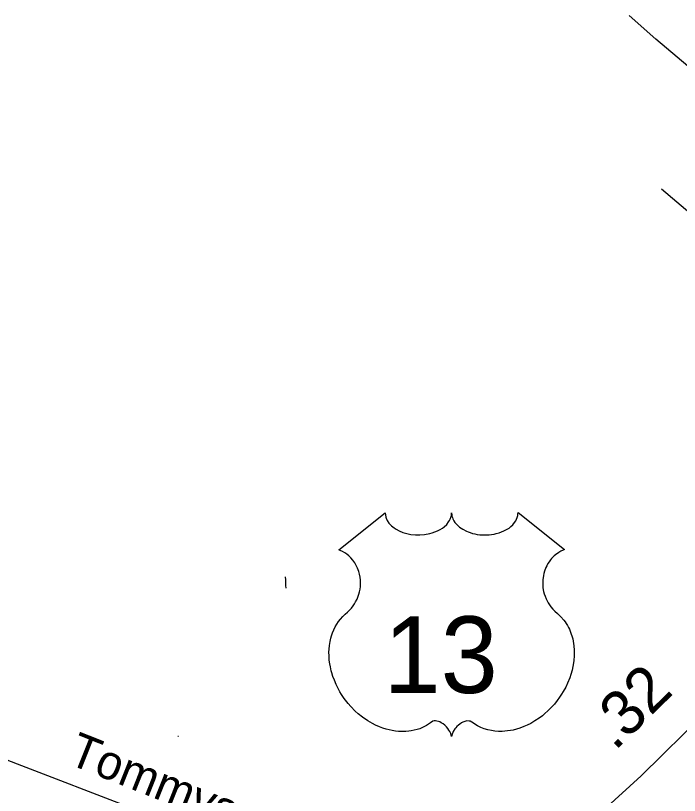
# Model space of a CAD drawing. Extents: x 2315291 to 2336543, y 597177 to 615230.
# Drawn here: x 2325292 to 2327131, y 602347 to 604507 of the extents above; entities that cross this region are included whole.
import ezdxf

# ---------------------------------------------------------------- set-up
doc = ezdxf.new("R2010")
doc.units = 0
for name, color, linetype in [('Exist Hydrographic Creek Single Shore', 7, 'Continuous'), ('Exist Road Non-System Type 51', 7, 'Continuous'), ('Exist Road Primary US Attributed', 7, 'Continuous'), ('Exist Road Primary US Mileage Tenths English Label', 7, 'Continuous'), ('Exist Road Primary US Shield CELL', 7, 'Continuous'), ('Exist Road Primary US Shield Number Label', 7, 'Continuous'), ('Exist Road Secondary Type 51 Attributed', 7, 'Continuous'), ('Exist Road Secondary Type 51 Label', 7, 'Continuous')]:
    doc.layers.add(name, color=color, linetype=linetype)

msp = doc.modelspace()

# ---------------------------------------------------------------- linework, layer by layer
at = {"layer": 'Exist Hydrographic Creek Single Shore'}
msp.add_lwpolyline([(2330983.5, 600534.7), (2330925.5, 600542.2), (2330547.5, 600822.3), (2330210.4, 601169.6), (2329763.4, 601712.7), (2329619.5, 601920.2), (2329459.3, 602110.6), (2329232.3, 602275.3), (2328880.5, 602461.4), (2328496.4, 602590.1), (2328144.3, 602763), (2328109.5, 602896.1), (2328072.4, 603219.6), (2327695.5, 603483.2), (2327485.3, 603638.8), (2327451.5, 603712.9), (2327081.3, 604026.1)], dxfattribs=at)
at = {"layer": 'Exist Road Non-System Type 51'}
msp.add_lwpolyline([(2327487.4, 604340.7), (2327469.1, 604290.7), (2327460.7, 604265.6), (2327450.7, 604250.6), (2327439.1, 604237.3), (2327420.7, 604228.9), (2327390.7, 604225.6), (2327355.7, 604227.3), (2327322.4, 604235.6), (2327285.7, 604250.6), (2327249, 604280.7), (2327184, 604341.5), (2327065.6, 604441.6), (2326992.3, 604506.7)], dxfattribs=at)
at = {"layer": 'Exist Road Primary US Attributed'}
msp.add_lwpolyline([(2326507.1, 601954.4), (2326687.2, 602106.2), (2326920.6, 602305.6), (2327025.6, 602400.6), (2327204, 602575.8), (2327489.1, 602864.4), (2327740.8, 603109.6)], dxfattribs=at)
at = {"layer": 'Exist Road Primary US Shield CELL'}
for p, q in [((2326187.4, 603026.9), (2326316, 603129.4)), ((2326316, 603129.4), (2326316.4, 603124)), ((2326499.5, 603122.5), (2326500, 603129.6)), ((2326500, 603129.6), (2326500.5, 603123.7)), ((2326683.3, 603121.5), (2326684, 603125.9)), ((2326684, 603125.9), (2326684.1, 603129.8)), ((2326684.1, 603129.8), (2326812.7, 603027.3)), ((2326316.4, 603124), (2326317.6, 603117.7)), ((2326317.6, 603117.7), (2326318.6, 603114.5)), ((2326318.6, 603114.5), (2326321.6, 603108.2)), ((2326321.6, 603108.2), (2326326.5, 603100.9)), ((2326486.4, 603097.1), (2326491.8, 603103.9)), ((2326491.8, 603103.9), (2326494.1, 603107.7)), ((2326494.1, 603107.7), (2326496.1, 603111.4)), ((2326496.1, 603111.4), (2326498.7, 603119.1)), ((2326498.7, 603119.1), (2326499.5, 603122.5)), ((2326500.5, 603123.7), (2326501.1, 603119.9)), ((2326501.1, 603119.9), (2326502.1, 603116.3)), ((2326502.1, 603116.3), (2326503.6, 603112.4)), ((2326503.6, 603112.4), (2326506.3, 603106.9)), ((2326506.3, 603106.9), (2326509.4, 603102.4)), ((2326674.7, 603102.3), (2326677.8, 603106.8)), ((2326677.8, 603106.8), (2326680, 603111.4)), ((2326680, 603111.4), (2326682.1, 603116.3)), ((2326682.1, 603116.3), (2326683.3, 603121.5)), ((2326326.5, 603100.9), (2326333.3, 603093.7)), ((2326333.3, 603093.7), (2326340.9, 603087.3)), ((2326340.9, 603087.3), (2326346.1, 603084)), ((2326346.1, 603084), (2326354.9, 603079.3)), ((2326460.9, 603079.1), (2326468.6, 603083.2)), ((2326468.6, 603083.2), (2326474.7, 603087.1)), ((2326474.7, 603087.1), (2326479.5, 603090.6)), ((2326479.5, 603090.6), (2326486.4, 603097.1)), ((2326509.4, 603102.4), (2326515.1, 603095.6)), ((2326515.1, 603095.6), (2326518.7, 603092.3)), ((2326518.7, 603092.3), (2326521.9, 603089.6)), ((2326521.9, 603089.6), (2326530.7, 603083.6)), ((2326530.7, 603083.6), (2326540.9, 603078.5)), ((2326644.6, 603079), (2326652.6, 603083.2)), ((2326652.6, 603083.2), (2326659.1, 603087.2)), ((2326659.1, 603087.2), (2326663.8, 603091)), ((2326663.8, 603091), (2326669.4, 603096.2)), ((2326669.4, 603096.2), (2326674.7, 603102.3)), ((2326354.9, 603079.3), (2326364.8, 603075.1)), ((2326364.8, 603075.1), (2326375.9, 603071.9)), ((2326375.9, 603071.9), (2326387.2, 603069.6)), ((2326387.2, 603069.6), (2326399.6, 603068.3)), ((2326399.6, 603068.3), (2326411.8, 603068)), ((2326411.8, 603068), (2326425, 603069)), ((2326425, 603069), (2326439.6, 603071.8)), ((2326439.6, 603071.8), (2326446.4, 603073.6)), ((2326446.4, 603073.6), (2326453.9, 603076.2)), ((2326453.9, 603076.2), (2326460.9, 603079.1)), ((2326540.9, 603078.5), (2326545.9, 603076.2)), ((2326545.9, 603076.2), (2326551.1, 603074.4)), ((2326551.1, 603074.4), (2326557.6, 603072.4)), ((2326557.6, 603072.4), (2326564.4, 603070.9)), ((2326564.4, 603070.9), (2326571.1, 603069.7)), ((2326571.1, 603069.7), (2326577.9, 603068.7)), ((2326577.9, 603068.7), (2326584.9, 603068.2)), ((2326584.9, 603068.2), (2326590.6, 603068)), ((2326590.6, 603068), (2326597.6, 603068.1)), ((2326597.6, 603068.1), (2326604, 603068.5)), ((2326604, 603068.5), (2326610.6, 603069.3)), ((2326610.6, 603069.3), (2326617.9, 603070.5)), ((2326617.9, 603070.5), (2326623.8, 603071.8)), ((2326623.8, 603071.8), (2326631.5, 603073.8)), ((2326631.5, 603073.8), (2326638.5, 603076.3)), ((2326638.5, 603076.3), (2326644.6, 603079)), ((2326191.4, 603025.3), (2326187.4, 603026.9)), ((2326197.7, 603022.2), (2326191.4, 603025.3)), ((2326204.2, 603018.3), (2326197.7, 603022.2)), ((2326209.4, 603014.5), (2326204.2, 603018.3)), ((2326797.1, 603019.5), (2326788.3, 603013.3)), ((2326802.7, 603022.8), (2326797.1, 603019.5)), ((2326809.6, 603026.2), (2326802.7, 603022.8)), ((2326812.7, 603027.3), (2326809.6, 603026.2)), ((2326214.9, 603010.3), (2326209.4, 603014.5)), ((2326220.6, 603004.6), (2326214.9, 603010.3)), ((2326226.3, 602998.2), (2326220.6, 603004.6)), ((2326231.7, 602990.4), (2326226.3, 602998.2)), ((2326774.1, 602998.9), (2326770.4, 602993.7)), ((2326777.2, 603002.5), (2326774.1, 602998.9)), ((2326780.7, 603006.3), (2326777.2, 603002.5)), ((2326784.5, 603009.8), (2326780.7, 603006.3)), ((2326788.3, 603013.3), (2326784.5, 603009.8)), ((2326236.7, 602981.9), (2326231.7, 602990.4)), ((2326239.6, 602975.7), (2326236.7, 602981.9)), ((2326242.8, 602967.2), (2326239.6, 602975.7)), ((2326761.4, 602977.9), (2326757.4, 602967.6)), ((2326763.8, 602982.9), (2326761.4, 602977.9)), ((2326767, 602988.6), (2326763.8, 602982.9)), ((2326770.4, 602993.7), (2326767, 602988.6)), ((2326244.8, 602959.8), (2326242.8, 602967.2)), ((2326246.5, 602951.2), (2326244.8, 602959.8)), ((2326754.3, 602955.5), (2326752.8, 602944)), ((2326755.5, 602961), (2326754.3, 602955.5)), ((2326757.4, 602967.6), (2326755.5, 602961)), ((2326247.4, 602942.4), (2326246.5, 602951.2)), ((2326247.3, 602925.6), (2326247.7, 602934.8)), ((2326247.7, 602934.8), (2326247.4, 602942.4)), ((2326752.8, 602944), (2326752.4, 602938.6)), ((2326752.4, 602938.6), (2326752.4, 602933.2)), ((2326752.4, 602933.2), (2326752.7, 602927.5)), ((2326243.3, 602904.3), (2326244.8, 602910.4)), ((2326244.8, 602910.4), (2326246.3, 602918.2)), ((2326246.3, 602918.2), (2326247.3, 602925.6)), ((2326752.7, 602927.5), (2326753.2, 602922)), ((2326753.2, 602922), (2326754.2, 602916.3)), ((2326754.2, 602916.3), (2326755.1, 602911.3)), ((2326755.1, 602911.3), (2326756.7, 602905.1)), ((2326234.1, 602882.5), (2326238, 602890)), ((2326238, 602890), (2326240.3, 602895.6)), ((2326240.3, 602895.6), (2326243.3, 602904.3)), ((2326756.7, 602905.1), (2326759, 602898)), ((2326759, 602898), (2326761.8, 602891.1)), ((2326761.8, 602891.1), (2326767.7, 602879.9)), ((2326222.7, 602865.5), (2326227.4, 602871.7)), ((2326227.4, 602871.7), (2326231.1, 602877.4)), ((2326231.1, 602877.4), (2326234.1, 602882.5)), ((2326767.7, 602879.9), (2326775.3, 602868.5)), ((2326775.3, 602868.5), (2326780.7, 602862.1)), ((2326198.3, 602842.2), (2326205.1, 602848.7)), ((2326205.1, 602848.7), (2326211.4, 602853.8)), ((2326211.4, 602853.8), (2326218.9, 602861.1)), ((2326218.9, 602861.1), (2326222.7, 602865.5)), ((2326780.7, 602862.1), (2326786, 602856.6)), ((2326786, 602856.6), (2326793.9, 602850)), ((2326793.9, 602850), (2326798.2, 602846.2)), ((2326798.2, 602846.2), (2326803.1, 602841.2)), ((2326181.6, 602821), (2326186.7, 602828.6)), ((2326186.7, 602828.6), (2326191.7, 602835.1)), ((2326191.7, 602835.1), (2326198.3, 602842.2)), ((2326803.1, 602841.2), (2326811.2, 602831.9)), ((2326811.2, 602831.9), (2326814.5, 602827.5)), ((2326814.5, 602827.5), (2326817.8, 602822.5)), ((2326169.7, 602796.5), (2326173.3, 602805.4)), ((2326173.3, 602805.4), (2326177.6, 602813.9)), ((2326177.6, 602813.9), (2326181.6, 602821)), ((2326817.8, 602822.5), (2326820.8, 602817.4)), ((2326820.8, 602817.4), (2326823.8, 602812)), ((2326823.8, 602812), (2326826.3, 602807.2)), ((2326826.3, 602807.2), (2326830.8, 602796.2)), ((2326163.1, 602772.7), (2326165.1, 602781.9)), ((2326165.1, 602781.9), (2326167, 602788.5)), ((2326167, 602788.5), (2326169.7, 602796.5)), ((2326830.8, 602796.2), (2326834.1, 602785.4)), ((2326834.1, 602785.4), (2326835.6, 602779.8)), ((2326835.6, 602779.8), (2326838, 602767.2)), ((2326160.4, 602751.9), (2326161.4, 602762)), ((2326161.4, 602762), (2326163.1, 602772.7)), ((2326838, 602767.2), (2326838.9, 602761)), ((2326838.9, 602761), (2326839.9, 602748.7)), ((2326160.1, 602743.2), (2326160.4, 602751.9)), ((2326160.3, 602732.8), (2326160.1, 602743.2)), ((2326839.9, 602748.7), (2326839.9, 602733.8)), ((2326161.1, 602721.5), (2326160.3, 602732.8)), ((2326162.5, 602710.7), (2326161.1, 602721.5)), ((2326838.8, 602719.6), (2326836.1, 602703.2)), ((2326839.9, 602733.8), (2326838.8, 602719.6)), ((2326164, 602702.9), (2326162.5, 602710.7)), ((2326166.4, 602691.9), (2326164, 602702.9)), ((2326833.9, 602693.3), (2326830.6, 602681.8)), ((2326836.1, 602703.2), (2326833.9, 602693.3)), ((2326168.1, 602685.6), (2326166.4, 602691.9)), ((2326171.3, 602675.7), (2326168.1, 602685.6)), ((2326175.1, 602665.3), (2326171.3, 602675.7)), ((2326827.3, 602671.8), (2326821.4, 602657.2)), ((2326830.6, 602681.8), (2326827.3, 602671.8)), ((2326180, 602653.9), (2326175.1, 602665.3)), ((2326183.8, 602646.1), (2326180, 602653.9)), ((2326821.4, 602657.2), (2326816.2, 602646.5)), ((2326190.6, 602633.6), (2326183.8, 602646.1)), ((2326195.3, 602625.9), (2326190.6, 602633.6)), ((2326809.4, 602634.1), (2326804.8, 602626.6)), ((2326816.2, 602646.5), (2326809.4, 602634.1)), ((2326202.5, 602615.3), (2326195.3, 602625.9)), ((2326213.8, 602600.7), (2326202.5, 602615.3)), ((2326792.7, 602609.2), (2326784.8, 602599.4)), ((2326799.4, 602618.5), (2326792.7, 602609.2)), ((2326804.8, 602626.6), (2326799.4, 602618.5)), ((2326220.9, 602592.6), (2326213.8, 602600.7)), ((2326233.2, 602580.1), (2326220.9, 602592.6)), ((2326775.3, 602588.9), (2326767.6, 602581.3)), ((2326784.8, 602599.4), (2326775.3, 602588.9)), ((2326241.5, 602572.6), (2326233.2, 602580.1)), ((2326252.8, 602563.4), (2326241.5, 602572.6)), ((2326751.5, 602567.3), (2326742.8, 602560.8)), ((2326757.6, 602572.3), (2326751.5, 602567.3)), ((2326767.6, 602581.3), (2326757.6, 602572.3)), ((2326267.9, 602553), (2326252.8, 602563.4)), ((2326280.7, 602545.6), (2326267.9, 602553)), ((2326288.8, 602541.4), (2326280.7, 602545.6)), ((2326436.3, 602543.7), (2326430.3, 602540)), ((2326441.8, 602547.5), (2326436.3, 602543.7)), ((2326447.6, 602551.7), (2326441.8, 602547.5)), ((2326451.9, 602552.7), (2326447.6, 602551.7)), ((2326455, 602552.8), (2326451.9, 602552.7)), ((2326458.8, 602552.5), (2326455, 602552.8)), ((2326463.5, 602551.3), (2326458.8, 602552.5)), ((2326467.3, 602549.9), (2326463.5, 602551.3)), ((2326471.4, 602547.8), (2326467.3, 602549.9)), ((2326476.6, 602544.6), (2326471.4, 602547.8)), ((2326481.4, 602540.7), (2326476.6, 602544.6)), ((2326522.5, 602544.1), (2326518.9, 602541.2)), ((2326527.3, 602547.2), (2326522.5, 602544.1)), ((2326530.8, 602549.1), (2326527.3, 602547.2)), ((2326536.8, 602551.5), (2326530.8, 602549.1)), ((2326542.5, 602552.7), (2326536.8, 602551.5)), ((2326548.7, 602552.4), (2326542.5, 602552.7)), ((2326551.3, 602551.7), (2326548.7, 602552.4)), ((2326555.9, 602549.3), (2326551.3, 602551.7)), ((2326571.8, 602539.2), (2326555.9, 602549.3)), ((2326719.3, 602546.1), (2326709.4, 602541)), ((2326731, 602552.8), (2326719.3, 602546.1)), ((2326742.8, 602560.8), (2326731, 602552.8)), ((2326300.5, 602536.4), (2326288.8, 602541.4)), ((2326309.9, 602532.8), (2326300.5, 602536.4)), ((2326318.6, 602530.1), (2326309.9, 602532.8)), ((2326327.1, 602527.8), (2326318.6, 602530.1)), ((2326335.2, 602525.9), (2326327.1, 602527.8)), ((2326344.9, 602524.5), (2326335.2, 602525.9)), ((2326352.7, 602523.8), (2326344.9, 602524.5)), ((2326359.5, 602523.3), (2326352.7, 602523.8)), ((2326366.7, 602523.2), (2326359.5, 602523.3)), ((2326373.6, 602523.4), (2326366.7, 602523.2)), ((2326381.3, 602524.1), (2326373.6, 602523.4)), ((2326388.4, 602525.3), (2326381.3, 602524.1)), ((2326396.5, 602526.9), (2326388.4, 602525.3)), ((2326404.4, 602528.9), (2326396.5, 602526.9)), ((2326411.7, 602531.3), (2326404.4, 602528.9)), ((2326417.9, 602533.8), (2326411.7, 602531.3)), ((2326423.2, 602536.2), (2326417.9, 602533.8)), ((2326430.3, 602540), (2326423.2, 602536.2)), ((2326485.5, 602536.8), (2326481.4, 602540.7)), ((2326489.9, 602531.6), (2326485.5, 602536.8)), ((2326492.8, 602527.6), (2326489.9, 602531.6)), ((2326495.5, 602523.1), (2326492.8, 602527.6)), ((2326497.9, 602517.7), (2326495.5, 602523.1)), ((2326503, 602520.4), (2326501.4, 602516.1)), ((2326504.6, 602523.7), (2326503, 602520.4)), ((2326509.1, 602530.8), (2326504.6, 602523.7)), ((2326511.4, 602533.5), (2326509.1, 602530.8)), ((2326514.5, 602537), (2326511.4, 602533.5)), ((2326518.9, 602541.2), (2326514.5, 602537)), ((2326581.2, 602534.6), (2326571.8, 602539.2)), ((2326590.5, 602531), (2326581.2, 602534.6)), ((2326600.7, 602527.9), (2326590.5, 602531)), ((2326610.5, 602525.9), (2326600.7, 602527.9)), ((2326620, 602524.5), (2326610.5, 602525.9)), ((2326629.9, 602523.7), (2326620, 602524.5)), ((2326639.9, 602523.7), (2326629.9, 602523.7)), ((2326647.4, 602524.2), (2326639.9, 602523.7)), ((2326655.1, 602525), (2326647.4, 602524.2)), ((2326663.3, 602526.2), (2326655.1, 602525)), ((2326670.2, 602527.6), (2326663.3, 602526.2)), ((2326689.1, 602532.9), (2326670.2, 602527.6)), ((2326700.5, 602537.2), (2326689.1, 602532.9)), ((2326709.4, 602541), (2326700.5, 602537.2)), ((2325741.4, 602510.9), (2325742.9, 602510.9)), ((2326499.9, 602509.7), (2326497.9, 602517.7)), ((2326501.4, 602516.1), (2326499.9, 602509.7))]:
    msp.add_line(p, q, dxfattribs=at)
msp.add_arc((2325617.2, 602916.3), 424.1, 0.5496, 4.8143, dxfattribs=at)
at = {"layer": 'Exist Road Secondary Type 51 Attributed'}
msp.add_lwpolyline([(2325206.8, 602468.2), (2325701.9, 602278), (2326218.6, 602070.4)], dxfattribs=at)

# ---------------------------------------------------------------- texts
at = {"layer": 'Exist Road Primary US Mileage Tenths English Label'}
msp.add_text('.32', height=125, rotation=44.5448, dxfattribs=at).set_placement((2326952.3, 602467.5))
at = {"layer": 'Exist Road Primary US Shield Number Label'}
msp.add_text('13', height=212.5, dxfattribs=at).set_placement((2326311.8, 602630.1))
at = {"layer": 'Exist Road Secondary Type 51 Label'}
msp.add_text('Tommys', height=95, rotation=338.3192, dxfattribs=at).set_placement((2325432.8, 602435.4))

doc.saveas('drawing.dxf')
